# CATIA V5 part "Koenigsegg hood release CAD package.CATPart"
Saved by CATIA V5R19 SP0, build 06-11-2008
Part number: Koenigsegg hood release package
Bounding box of the stored display mesh (mm): x 1170.527 to 2900, y -976.486 to -468.23, z 100 to 920.92
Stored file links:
  X:\Henrik.l\Personal requests\Jon\GrabCAD\Koenigsegg hood release package.CATPart
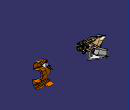
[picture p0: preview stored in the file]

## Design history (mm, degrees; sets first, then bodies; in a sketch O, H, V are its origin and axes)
Set1 "140-821-1202 Rocker LH.1\\FINAL RESULT"
  DatumSurface1 "Split.95"
Set2 "130-821-1032 Rocker striker box LH.1\\Geometrical Set.1"
  DatumSurface2 "STRIKER BOX LH - REV AD"
Set3 "130-821-1012 Rocker hinge box LH.1\\Geometrical Set.1"
  DatumSurface3 "130-821-1012-AF Rocker hinge box LH"
Set4 "130-811-6101 Dashboard carcass.1\\Main surf"
  Set5 "130-811-6101-AL Dashboard carcass"
    DatumSurface4 "Split.8"
Body1 (main body)
Body2 "140 Hinge Assy LH open.1\\Main Arm\\NAUO59\\NONE"
  Solid1 "Solid.1": solid without history
Body3 "140 Hinge Assy LH open.1\\Base\\NAUO57\\NONE"
  Solid2 "Solid.1": solid without history
Body4 "140 Hinge Assy LH open.1\\Base\\NAUO63\\NONE"
  Solid3 "Solid.1": solid without history
Body5 "140 Hinge Assy LH closed.1\\Main Arm\\NAUO59\\NONE"
  Solid4 "Solid.1": solid without history
Body6 "8344-005 Hood opening handle.1\\PartBody"
  Solid5 "Solid.1": solid without history
Body7 "8344-005 Hood opening handle.1\\PartBody"
  Solid6 "Solid.1": solid without history
Body8 "8342-012 hood opener bracket.1\\NAUO2\\Process-Bends1"
  Solid7 "Solid.1": solid without history
Body9 "8342-012 hood opener bracket.1\\NAUO1\\Cut-Extrude1"
  Solid8 "Solid.1": solid without history
Body10 "8342-012 hood opener bracket.2\\NAUO2\\Process-Bends1"
  Solid9 "Solid.1": solid without history
Body11 "8342-012 hood opener bracket.2\\NAUO1\\Cut-Extrude1"
  Solid10 "Solid.1": solid without history
Body12 "8344-005 Hood opening handle.2\\PartBody"
  Solid11 "Solid.1": solid without history
Body13 "8344-005 Hood opening handle.2\\PartBody"
  Solid12 "Solid.1": solid without history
